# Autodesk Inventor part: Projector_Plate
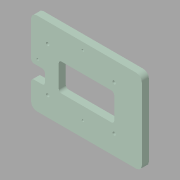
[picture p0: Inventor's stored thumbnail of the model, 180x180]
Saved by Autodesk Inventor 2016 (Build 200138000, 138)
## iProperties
Created: 2016-01
Part Number: Projector_Plate
Material: Generic
Document SubType Name: Modeling
Designer: John
Density: 1 g/cm^3
Appearance: Default
Author: John
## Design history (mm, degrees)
feature "SOLID1"
sketch "Sketch1"
  geometry: L1 (-10, 140)-(-10, 10) reference; L2 (0, 0)-(180, 0) reference; L3 (190, 10)-(190, 140) reference; L4 (180, 150)-(0, 150) reference; L5 (135, 50)-(45, 50) reference; L6 (40, 55)-(40, 95) reference; L7 (45, 100)-(135, 100) reference; L8 (140, 95)-(140, 55) reference; L9 (-10, 72)-(15, 72); L10 (15, 72)-(15, 47); L11 (15, 47)-(-10, 47); L12 (-10, 47)-(-10, 72); C1 r 3 at (20, 115) reference; C2 r 3 at (140, 115) reference; C3 r 3 at (140, 35) reference; C4 r 3 at (20, 35) reference; C5 r 2 at (83.5, 27) reference; C6 r 2 at (2, 82) reference; C7 r 2 at (83.5, 137.05) reference; A1 r 10 centre (0, 140) between (0, 150) and (-10, 140) reference; A2 r 10 centre (0, 10) between (-10, 10) and (0, 0) reference; A3 r 10 centre (180, 10) between (180, 0) and (190, 10) reference; A4 r 10 centre (180, 140) between (190, 140) and (180, 150) reference; A5 r 5 centre (45, 55) between (40, 55) and (45, 50) reference; A6 r 5 centre (45, 95) between (45, 100) and (40, 95) reference; A7 r 5 centre (135, 95) between (140, 95) and (135, 100) reference; A8 r 5 centre (135, 55) between (135, 50) and (140, 55) reference; 1 further point
  constraints: 8 end point, 2 parallel, 1 horizontal, 1 perpendicular, 1 point on line
  dimensions: "d0" = 10 distance from line of C6.centre L9; "d1" = 25 distance of L9.end L10.end; "d2" = 25 distance of L10.end L11.end
extrude "Extrusion1" cut sketch "Sketch1" stored distance "d3" = 10; taper "d4" = 0 deg
fillet "Fillet1" dims "d5" = 5
body "Solid1"
node "Projected Loop1"
